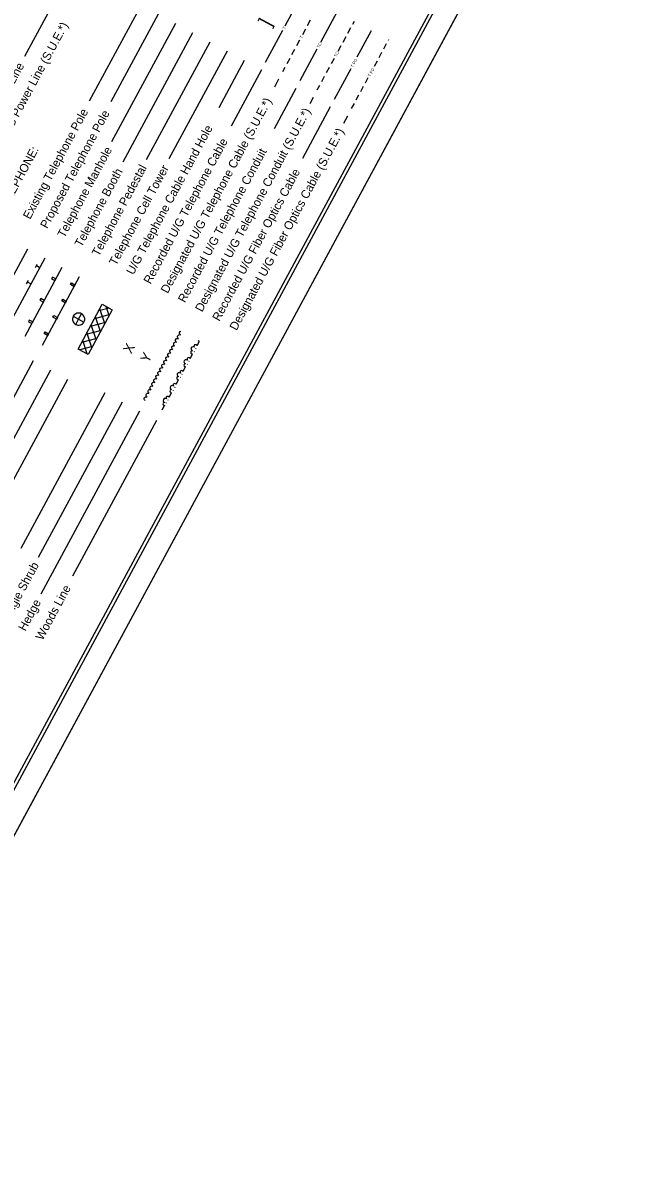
# Model space of a CAD drawing. Extents: x 1376167 to 1379209, y 761324 to 763997.
# Drawn here: x 1378596 to 1379209, y 761324 to 762484 of the extents above; entities that cross this region are included whole.
import ezdxf

# ---------------------------------------------------------------- set-up
doc = ezdxf.new("R2010")
doc.units = 0
for name, color, linetype in [('Sheet Cutting Line CELL', 7, 'Continuous'), ('Sheet Plot Border Inside CELL', 7, 'Continuous'), ('Sheet Plot Border Outside CELL', 7, 'Continuous'), ('Sheet Symbology CELL', 7, 'Continuous')]:
    doc.layers.add(name, color=color, linetype=linetype)

msp = doc.modelspace()

# ---------------------------------------------------------------- linework, layer by layer
at = {"layer": 'Sheet Cutting Line CELL'}
msp.add_line((1378410.2, 761323.6), (1379209.3, 762805.9), dxfattribs=at)
at = {"layer": 'Sheet Plot Border Inside CELL'}
msp.add_lwpolyline([(1378396.6, 761345.7), (1379187.4, 762812.6), (1378258.7, 763313.3), (1377467.8, 761846.4)], close=True, dxfattribs=at)
at = {"layer": 'Sheet Plot Border Outside CELL'}
msp.add_lwpolyline([(1378410.2, 761323.6), (1379209.3, 762805.9), (1378241, 763327.9), (1377441.9, 761845.6)], close=True, dxfattribs=at)
at = {"layer": 'Sheet Symbology CELL'}
for p, q in [((1378646.4, 762540), (1378597.5, 762449.3)), ((1378864.3, 762480.6), (1378882.3, 762513.9)), ((1378716.8, 762502), (1378663.7, 762403.5)), ((1378734.4, 762492.5), (1378686, 762402.7)), ((1378887.2, 762481), (1378890.3, 762486.8)), ((1378900.7, 762463.8), (1378917.5, 762494.9)), ((1378933.4, 762482.4), (1378935.1, 762485.5)), ((1378752, 762483), (1378686.6, 762361.7)), ((1378769.6, 762473.5), (1378698.2, 762341.1)), ((1378844.3, 762443.5), (1378861.9, 762476.2)), ((1378882.3, 762471.8), (1378885.3, 762477.5)), ((1378928.5, 762473.2), (1378931.5, 762478.9)), ((1378938.1, 762449), (1378952.7, 762476)), ((1378787.2, 762464), (1378722.1, 762343.3)), ((1378876.1, 762460.4), (1378879.2, 762466.2)), ((1378923.5, 762464), (1378926.6, 762469.7)), ((1378965.2, 762457.1), (1378968.1, 762462.4)), ((1378970, 762465.9), (1378970.3, 762466.5)), ((1378804.8, 762454.6), (1378745.4, 762344.3)), ((1378871.2, 762451.2), (1378874.2, 762456.9)), ((1378879.5, 762424.5), (1378897.1, 762457.2)), ((1378918.5, 762454.7), (1378921.6, 762460.4)), ((1378960.5, 762448.3), (1378963.3, 762453.6)), ((1378822.4, 762445.1), (1378796.3, 762396.6)), ((1378861.9, 762434), (1378864.3, 762438.4)), ((1378866.2, 762442), (1378869.3, 762447.7)), ((1378906.6, 762432.7), (1378909.7, 762438.4)), ((1378911.6, 762442), (1378914.7, 762447.7)), ((1378955.7, 762439.5), (1378958.6, 762444.8)), ((1378840, 762435.6), (1378808.9, 762377.9)), ((1378901.7, 762423.5), (1378904.7, 762429.2)), ((1378914.7, 762405.5), (1378931.7, 762437.1)), ((1378946.5, 762422.3), (1378949.3, 762427.6)), ((1378875.2, 762416.6), (1378853, 762375.3)), ((1378857.6, 762426.1), (1378853.3, 762418)), ((1378897.1, 762415), (1378899.8, 762420)), ((1378941.7, 762413.5), (1378944.6, 762418.8)), ((1378892.8, 762407.1), (1378889.5, 762400.9)), ((1378937, 762404.7), (1378939.8, 762410)), ((1378910.4, 762397.6), (1378881.9, 762344.8)), ((1378932.3, 762396.1), (1378935.1, 762401.2)), ((1378928, 762388.1), (1378924, 762380.6)), ((1378562.9, 762181.9), (1378600.9, 762252.3)), ((1378618.5, 762242.8), (1378580.5, 762172.4)), ((1378598.2, 762162.9), (1378636.1, 762233.3)), ((1378608.7, 762233), (1378610.6, 762236.5)), ((1378613.2, 762232.9), (1378609.7, 762234.8)), ((1378599.7, 762216.3), (1378601.6, 762219.8)), ((1378604.1, 762216.2), (1378600.7, 762218)), ((1378615.8, 762153.4), (1378653.7, 762223.8)), ((1378652.4, 762149.5), (1378677.1, 762195.4)), ((1378677.1, 762195.4), (1378687.4, 762189.8)), ((1378647.4, 762183.2), (1378652.9, 762180.2)), ((1378652.9, 762180.2), (1378655.9, 762185.7)), ((1378687.4, 762189.8), (1378662.7, 762144)), ((1378684.7, 762184.8), (1378669.2, 762180.6)), ((1378684.1, 762191.6), (1378673.6, 762188.8)), ((1378679.8, 762175.6), (1378674.7, 762190.8)), ((1378684.2, 762183.8), (1378681, 762193.3)), ((1378650, 762174.7), (1378652.9, 762180.2)), ((1378652.9, 762180.2), (1378658.4, 762177.2)), ((1378680.3, 762176.6), (1378664.8, 762172.5)), ((1378671, 762159.3), (1378665.9, 762174.5)), ((1378675.4, 762167.5), (1378670.3, 762182.7)), ((1378671.5, 762160.3), (1378656, 762156.1)), ((1378675.9, 762168.4), (1378660.4, 762164.3)), ((1378666.6, 762151.1), (1378661.5, 762166.4)), ((1378752.2, 762159), (1378752.7, 762159.9)), ((1378752.7, 762159.9), (1378753.5, 762160.3)), ((1378753.5, 762160.3), (1378754.3, 762160.5)), ((1378754.2, 762162.8), (1378754.7, 762163.6)), ((1378754.2, 762161.9), (1378754.2, 762162.8)), ((1378754.5, 762161), (1378754.2, 762161.9)), ((1378754.3, 762160.5), (1378755.2, 762160.3)), ((1378755.2, 762160.3), (1378754.5, 762161)), ((1378754.7, 762163.6), (1378755.5, 762164.1)), ((1378755.5, 762164.1), (1378756.3, 762164.3)), ((1378756.2, 762166.5), (1378756.7, 762167.4)), ((1378756.3, 762165.6), (1378756.2, 762166.5)), ((1378756.5, 762164.8), (1378756.3, 762165.6)), ((1378756.3, 762164.3), (1378757.2, 762164)), ((1378757.2, 762164.1), (1378756.5, 762164.8)), ((1378756.7, 762167.4), (1378757.5, 762167.8)), ((1378757.5, 762167.8), (1378757.6, 762167.8)), ((1378662.7, 762144), (1378652.4, 762149.5)), ((1378653, 762149.2), (1378652.7, 762150)), ((1378667.1, 762152.1), (1378654, 762148.6)), ((1378661.7, 762144.5), (1378657.1, 762158.2)), ((1378746.2, 762147.8), (1378746.6, 762148.7)), ((1378746.6, 762148.7), (1378747.4, 762149.1)), ((1378747.4, 762149.1), (1378748.3, 762149.3)), ((1378748.2, 762151.6), (1378748.6, 762152.4)), ((1378748.2, 762150.6), (1378748.2, 762151.6)), ((1378748.5, 762149.8), (1378748.2, 762150.6)), ((1378748.3, 762149.3), (1378749.1, 762149.1)), ((1378749.2, 762149.1), (1378748.5, 762149.8)), ((1378748.6, 762152.4), (1378749.4, 762152.9)), ((1378749.4, 762152.9), (1378750.3, 762153)), ((1378750.2, 762155.3), (1378750.6, 762156.1)), ((1378750.2, 762154.4), (1378750.2, 762155.3)), ((1378750.5, 762153.5), (1378750.2, 762154.4)), ((1378750.3, 762153), (1378751.1, 762152.8)), ((1378751.2, 762152.8), (1378750.5, 762153.5)), ((1378750.6, 762156.1), (1378751.5, 762156.6)), ((1378751.5, 762156.6), (1378752.3, 762156.8)), ((1378752.2, 762158.1), (1378752.2, 762159)), ((1378752.5, 762157.3), (1378752.2, 762158.1)), ((1378752.3, 762156.8), (1378753.1, 762156.6)), ((1378753.2, 762156.6), (1378752.5, 762157.3)), ((1378772.9, 762149.9), (1378773.1, 762150.3)), ((1378774.1, 762153.2), (1378776.5, 762157.6)), ((1378606.5, 762137.4), (1378557, 762045.6)), ((1378740.1, 762136.6), (1378740.6, 762137.4)), ((1378740.1, 762135.7), (1378740.1, 762136.6)), ((1378740.6, 762137.4), (1378741.4, 762137.9)), ((1378741.4, 762137.9), (1378742.2, 762138.1)), ((1378742.1, 762140.3), (1378742.6, 762141.2)), ((1378742.1, 762139.4), (1378742.1, 762140.3)), ((1378742.4, 762138.6), (1378742.1, 762139.4)), ((1378742.2, 762138.1), (1378743.1, 762137.8)), ((1378743.1, 762137.9), (1378742.4, 762138.6)), ((1378742.6, 762141.2), (1378743.4, 762141.6)), ((1378743.4, 762141.6), (1378744.2, 762141.8)), ((1378744.1, 762144.1), (1378744.6, 762144.9)), ((1378744.2, 762143.2), (1378744.1, 762144.1)), ((1378744.4, 762142.3), (1378744.2, 762143.2)), ((1378744.2, 762141.8), (1378745.1, 762141.6)), ((1378745.1, 762141.6), (1378744.4, 762142.3)), ((1378744.6, 762144.9), (1378745.4, 762145.4)), ((1378745.4, 762145.4), (1378746.2, 762145.6)), ((1378746.2, 762146.9), (1378746.2, 762147.8)), ((1378746.5, 762146.1), (1378746.2, 762146.9)), ((1378746.2, 762145.6), (1378747.1, 762145.3)), ((1378747.2, 762145.4), (1378746.5, 762146.1)), ((1378765.8, 762136.7), (1378766, 762137.1)), ((1378767, 762140), (1378769.4, 762144.4)), ((1378771.2, 762146.8), (1378771.5, 762147.2)), ((1378624.1, 762127.9), (1378556.4, 762002.4)), ((1378734.1, 762125.4), (1378734.5, 762126.2)), ((1378734.1, 762124.5), (1378734.1, 762125.4)), ((1378734.5, 762126.2), (1378735.3, 762126.7)), ((1378735.3, 762126.7), (1378736.2, 762126.9)), ((1378736.1, 762129.1), (1378736.5, 762130)), ((1378736.1, 762128.2), (1378736.1, 762129.1)), ((1378736.4, 762127.4), (1378736.1, 762128.2)), ((1378736.2, 762126.9), (1378737, 762126.6)), ((1378737.1, 762126.6), (1378736.4, 762127.4)), ((1378736.5, 762130), (1378737.3, 762130.4)), ((1378737.3, 762130.4), (1378738.2, 762130.6)), ((1378738.1, 762132.9), (1378738.5, 762133.7)), ((1378738.1, 762131.9), (1378738.1, 762132.9)), ((1378738.4, 762131.1), (1378738.1, 762131.9)), ((1378738.2, 762130.6), (1378739, 762130.4)), ((1378739.1, 762130.4), (1378738.4, 762131.1)), ((1378738.5, 762133.7), (1378739.4, 762134.2)), ((1378739.4, 762134.2), (1378740.2, 762134.3)), ((1378740.4, 762134.8), (1378740.1, 762135.7)), ((1378740.2, 762134.3), (1378741, 762134.1)), ((1378741.1, 762134.1), (1378740.4, 762134.8)), ((1378759.9, 762126.8), (1378762.3, 762131.2)), ((1378764.1, 762133.6), (1378764.3, 762134)), ((1378641.7, 762118.4), (1378574, 761992.9)), ((1378728, 762114.2), (1378728.5, 762115)), ((1378728, 762113.2), (1378728, 762114.2)), ((1378728.3, 762112.4), (1378728, 762113.2)), ((1378728.5, 762115), (1378729.3, 762115.5)), ((1378729.3, 762115.5), (1378730.1, 762115.6)), ((1378730, 762117.9), (1378730.5, 762118.7)), ((1378730, 762117), (1378730, 762117.9)), ((1378730.3, 762116.1), (1378730, 762117)), ((1378730.1, 762115.6), (1378731, 762115.4)), ((1378731, 762115.4), (1378730.3, 762116.1)), ((1378730.5, 762118.7), (1378731.3, 762119.2)), ((1378731.3, 762119.2), (1378732.1, 762119.4)), ((1378732, 762121.6), (1378732.5, 762122.5)), ((1378732.1, 762120.7), (1378732, 762121.6)), ((1378732.3, 762119.9), (1378732.1, 762120.7)), ((1378732.1, 762119.4), (1378733, 762119.1)), ((1378733, 762119.2), (1378732.3, 762119.9)), ((1378732.5, 762122.5), (1378733.3, 762122.9)), ((1378733.3, 762122.9), (1378734.1, 762123.1)), ((1378734.4, 762123.6), (1378734.1, 762124.5)), ((1378734.1, 762123.1), (1378735, 762122.9)), ((1378735.1, 762122.9), (1378734.4, 762123.6)), ((1378752.8, 762113.6), (1378755.2, 762118)), ((1378757, 762120.4), (1378757.2, 762120.8)), ((1378758.7, 762123.5), (1378758.9, 762123.9)), ((1378679.8, 762104.8), (1378593.9, 761945.4)), ((1378722, 762102.9), (1378722.4, 762103.8)), ((1378722, 762102), (1378722, 762102.9)), ((1378722.3, 762101.2), (1378722, 762102)), ((1378722.4, 762103.8), (1378723.2, 762104.2)), ((1378723.2, 762104.2), (1378724.1, 762104.4)), ((1378724, 762106.7), (1378724.4, 762107.5)), ((1378724, 762105.8), (1378724, 762106.7)), ((1378724.3, 762104.9), (1378724, 762105.8)), ((1378724.1, 762104.4), (1378724.9, 762104.2)), ((1378725, 762104.2), (1378724.3, 762104.9)), ((1378724.4, 762107.5), (1378725.2, 762108)), ((1378725.2, 762108), (1378726.1, 762108.1)), ((1378726, 762110.4), (1378726.4, 762111.2)), ((1378726, 762109.5), (1378726, 762110.4)), ((1378726.3, 762108.7), (1378726, 762109.5)), ((1378726.1, 762108.1), (1378726.9, 762107.9)), ((1378727, 762107.9), (1378726.3, 762108.7)), ((1378726.4, 762111.2), (1378727.3, 762111.7)), ((1378727.3, 762111.7), (1378728.1, 762111.9)), ((1378728.1, 762111.9), (1378728.9, 762111.7)), ((1378729, 762111.7), (1378728.3, 762112.4)), ((1378745.7, 762100.4), (1378748, 762104.8)), ((1378749.9, 762107.2), (1378750.1, 762107.6)), ((1378751.5, 762110.3), (1378751.8, 762110.7)), ((1378697.5, 762095.3), (1378611.5, 761935.9)), ((1378719.9, 762099.2), (1378720.4, 762100)), ((1378720, 762098.3), (1378719.9, 762099.2)), ((1378720.2, 762097.4), (1378720, 762098.3)), ((1378720.9, 762096.7), (1378720.2, 762097.4)), ((1378720.4, 762100), (1378721.2, 762100.5)), ((1378721.2, 762100.5), (1378722, 762100.7)), ((1378722, 762100.7), (1378722.9, 762100.4)), ((1378723, 762100.5), (1378722.3, 762101.2)), ((1378738.5, 762087.2), (1378740.9, 762091.6)), ((1378742.8, 762094), (1378743, 762094.4)), ((1378744.4, 762097.1), (1378744.7, 762097.5)), ((1378715.1, 762085.8), (1378614.1, 761898.6)), ((1378732.7, 762076.3), (1378646.7, 761916.9))]:
    msp.add_line(p, q, dxfattribs=at)
for points in [[(1378255, 763301.1), (1377543.2, 761980.7), (1378466.5, 761482.9), (1379178.3, 762803.3)], [(1378628.7, 762219.7), (1378629.7, 762221.4), (1378626.2, 762223.3), (1378625.2, 762221.6)], [(1378644.7, 762215.6), (1378645.7, 762217.3), (1378649.2, 762215.4), (1378648.2, 762213.7)], [(1378616.9, 762197.7), (1378617.8, 762199.4), (1378614.3, 762201.3), (1378613.4, 762199.6)], [(1378635.7, 762198.9), (1378636.7, 762200.6), (1378640.2, 762198.7), (1378639.2, 762197)], [(1378626.7, 762182.1), (1378627.6, 762183.9), (1378631.2, 762182), (1378630.2, 762180.2)], [(1378605, 762175.7), (1378606, 762177.4), (1378602.4, 762179.3), (1378601.5, 762177.6)], [(1378617.7, 762165.4), (1378618.6, 762167.2), (1378622.1, 762165.3), (1378621.2, 762163.5)]]:
    msp.add_lwpolyline(points, close=True, dxfattribs=at)
for centre, radius, start, end in [((1378652.9, 762180.2), 6.25, 151.6646, 241.6692), ((1378652.9, 762180.2), 6.25, 61.6646, 151.6692), ((1378652.9, 762180.2), 6.25, 331.6646, 61.6692), ((1378652.9, 762180.2), 6.25, 241.6646, 331.6692), ((1378770, 762149.8), 2.06, 47.634, 255.7065), ((1378772.5, 762152.4), 1.58, 22.4387, 223.2353), ((1378776.3, 762159.4), 1.58, 217.9213, 265.4192), ((1378762.8, 762136.6), 2.06, 47.634, 255.7065), ((1378765.4, 762139.2), 1.58, 22.4387, 223.2353), ((1378769.2, 762146.2), 1.58, 80.1052, 280.9018), ((1378755.7, 762123.3), 2.06, 47.634, 255.7065), ((1378758.3, 762126), 1.58, 22.4387, 223.2353), ((1378762.1, 762133), 1.58, 80.1052, 280.9018), ((1378751.1, 762112.7), 1.58, 22.4387, 223.2353), ((1378754.9, 762119.8), 1.58, 80.1052, 280.9018), ((1378747.8, 762106.6), 1.58, 80.1052, 280.9018), ((1378748.6, 762110.1), 2.06, 47.634, 255.7065), ((1378740.7, 762093.4), 1.58, 80.1052, 280.9018), ((1378741.5, 762096.9), 2.06, 47.634, 255.7065), ((1378744, 762099.5), 1.58, 22.4387, 223.2353)]:
    msp.add_arc(centre, radius, start, end, dxfattribs=at)

# ---------------------------------------------------------------- texts
for s, height, p in [(']', 13.5, (1378848.4, 762479.1)), ('Designated U/G Power Line (S.U.E.*)', 8.75, (1378550.4, 762310.3)), ('T', 3, (1378864, 762476.8)), ('T', 3, (1378881.6, 762467.4)), ('TC', 3, (1378899.1, 762457.6)), ('TC', 3, (1378916.8, 762448.4)), ('Recorded U/G Power Line', 8.75, (1378532.8, 762319.8)), ('T FO', 3, (1378933.8, 762437.7)), ('T FO', 3, (1378951.4, 762428.2)), ('Designated U/G Telephone Cable (S.U.E.*)', 8.75, (1378744.1, 762205.9)), ('Existing Telephone Pole', 8.75, (1378603.2, 762281.8)), ('Proposed Telephone Pole', 8.75, (1378620.8, 762272.3)), ('Designated U/G Telephone Conduit (S.U.E.*)', 8.75, (1378779.3, 762186.9)), ('U/G Telephone Cable Hand Hole', 8.75, (1378708.9, 762224.9)), ('Designated U/G Fiber Optics Cable (S.U.E.*)', 8.75, (1378814.5, 762167.9)), ('Recorded U/G Telephone Cable', 8.75, (1378726.5, 762215.4)), ('TELEPHONE:', 8.75, (1378577.3, 762288.9)), ('Telephone Manhole', 8.75, (1378638.4, 762262.8)), ('Recorded U/G Telephone Conduit', 8.75, (1378761.7, 762196.4)), ('Telephone Booth', 8.75, (1378656, 762253.3)), ('Telephone Pedestal', 8.75, (1378673.6, 762243.8)), ('Telephone Cell Tower', 8.75, (1378691.3, 762234.4)), ('Recorded U/G Fiber Optics Cable', 8.75, (1378796.9, 762177.4)), ('X', 10, (1378706.7, 762144.1)), ('Y', 10, (1378724.3, 762134.6)), ('Single Shrub', 8.75, (1378580.8, 761869.4)), ('Woods Line', 8.75, (1378616, 761850.5)), ('Hedge', 8.75, (1378598.4, 761859.9))]:
    msp.add_text(s, height=height, rotation=61.6702, dxfattribs=at).set_placement(p)

doc.saveas('drawing.dxf')
